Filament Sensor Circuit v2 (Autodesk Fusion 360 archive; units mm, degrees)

design "Filament Sensor Circuit"
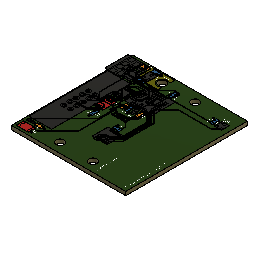
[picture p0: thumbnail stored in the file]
sketch "Outline" plane through (0, 0, 0) normal (0, 0, 1) x axis (1, 0, 0)
  line L1 (-12, 0) -> (-12, 50)
  line L2 (35, 0) -> (-12, 0)
  line L3 (35, 50) -> (35, 0)
  line L4 (-12, 50) -> (35, 50)
canvas "Canvas1" bodies "Board"
canvas "Canvas2" bodies "Board"
pcbhole "PCBHole1" HoleDepth 1.615 HoleDiameter 3.25 TipAngle 10313.2
pcbhole "PCBHole2" HoleDepth 1.615 HoleDiameter 3.25 TipAngle 10313.2
pcbhole "PCBHole3" HoleDepth 1.615 HoleDiameter 3.25 TipAngle 10313.2
pcbhole "PCBHole4" HoleDepth 1.615 HoleDiameter 3.25 TipAngle 10313.2
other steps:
pcbextrude "PCBExtrude"
pcbextrude "PCBExtrude1"
pcbextrude "PCBExtrude1"
box_primitive "BoxPrimitive1" DistanceX 9.3302 DistanceY 32.447 DistanceZ 0.1 OffsetDistanceX 0 OffsetDistanceY 0
box_primitive "BoxPrimitive1" DistanceX 6.0815 DistanceY 2.27 DistanceZ 2.5106 OffsetDistanceX 0 OffsetDistanceY 0
box_primitive "BoxPrimitive1" DistanceX 5.8 DistanceY 3.5135 DistanceZ 0.1 OffsetDistanceX 0 OffsetDistanceY 0
box_primitive "BoxPrimitive1" DistanceX 9.527 DistanceY 6.427 DistanceZ 0.1 OffsetDistanceX 0 OffsetDistanceY 0
box_primitive "BoxPrimitive1" DistanceX 2.8 DistanceY 1 DistanceZ 0.1 OffsetDistanceX 0 OffsetDistanceY 0
box_primitive "BoxPrimitive1" DistanceX 10.98 DistanceY 9.96 DistanceZ 0.1 OffsetDistanceX 0 OffsetDistanceY 0
box_primitive "BoxPrimitive1" DistanceX 2.8 DistanceY 1.3 DistanceZ 0.1 OffsetDistanceX 0 OffsetDistanceY 0
box_primitive "BoxPrimitive1" DistanceX 5 DistanceY 3.127 DistanceZ 0.1 OffsetDistanceX 0 OffsetDistanceY 0
box_primitive "BoxPrimitive1" DistanceX 3.2404 DistanceY 3.8664 DistanceZ 0.1 OffsetDistanceX 0 OffsetDistanceY 0
box_primitive "BoxPrimitive1" DistanceX 6.0674 DistanceY 6.4262 DistanceZ 0.1 OffsetDistanceX 0 OffsetDistanceY 0
box_primitive "BoxPrimitive1" DistanceX 2.9972 DistanceY 3.216 DistanceZ 0.1 OffsetDistanceX 0 OffsetDistanceY 0
extrude "Extrude1" sketch "Outline" blind 1.5 bodies "Board"
pcbextrude "PCBExtrude1"
pcbextrude "PCBExtrude1"
pcbhole "PCBHole1" HoleDepth 0.063 HoleDiameter 3.25 TipAngle 10313.2
pcbhole "PCBHole1" HoleDepth 0.063 HoleDiameter 3.25 TipAngle 10313.2
pcbhole "PCBHole2" HoleDepth 0.063 HoleDiameter 3.25 TipAngle 10313.2
pcbhole "PCBHole2" HoleDepth 0.063 HoleDiameter 3.25 TipAngle 10313.2
pcbhole "PCBHole3" HoleDepth 0.063 HoleDiameter 3.25 TipAngle 10313.2
pcbhole "PCBHole3" HoleDepth 0.063 HoleDiameter 3.25 TipAngle 10313.2
pcbhole "PCBHole4" HoleDepth 0.063 HoleDiameter 3.25 TipAngle 10313.2
pcbhole "PCBHole4" HoleDepth 0.063 HoleDiameter 3.25 TipAngle 10313.2
pcbextrude "PCBExtrude2" bodies "CopperHoles"
create_component "CreateComponent1"
create_component "CreateComponent2"
create_component "CreateComponent3"
create_component "CreateComponent4"
create_component "CreateComponent5"
create_component "CreateComponent6"
create_component "CreateComponent1"
create_component "CreateComponent2"
create_component "CreateComponent3"
create_component "CreateComponent4"
create_component "CreateComponent5"
create_component "CreateComponent6"
create_component "CreateComponent7"
create_component "CreateComponent8"
create_component "CreateComponent9"
create_component "CreateComponent10"
create_component "CreateComponent11"
as_built_joint "As-built1"
named bodies: "Board", "CopperHoles"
